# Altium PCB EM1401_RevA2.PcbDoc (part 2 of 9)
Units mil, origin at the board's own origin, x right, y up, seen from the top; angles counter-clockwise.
Board outline 7800 x 5300 mil, 6 copper layers (Top Layer, MidLayer1, MidLayer2, MidLayer3, MidLayer4, Bottom Layer), stack 16.8 mil thick; 751 components, 531 nets, 2554 pads, 1388 vias.
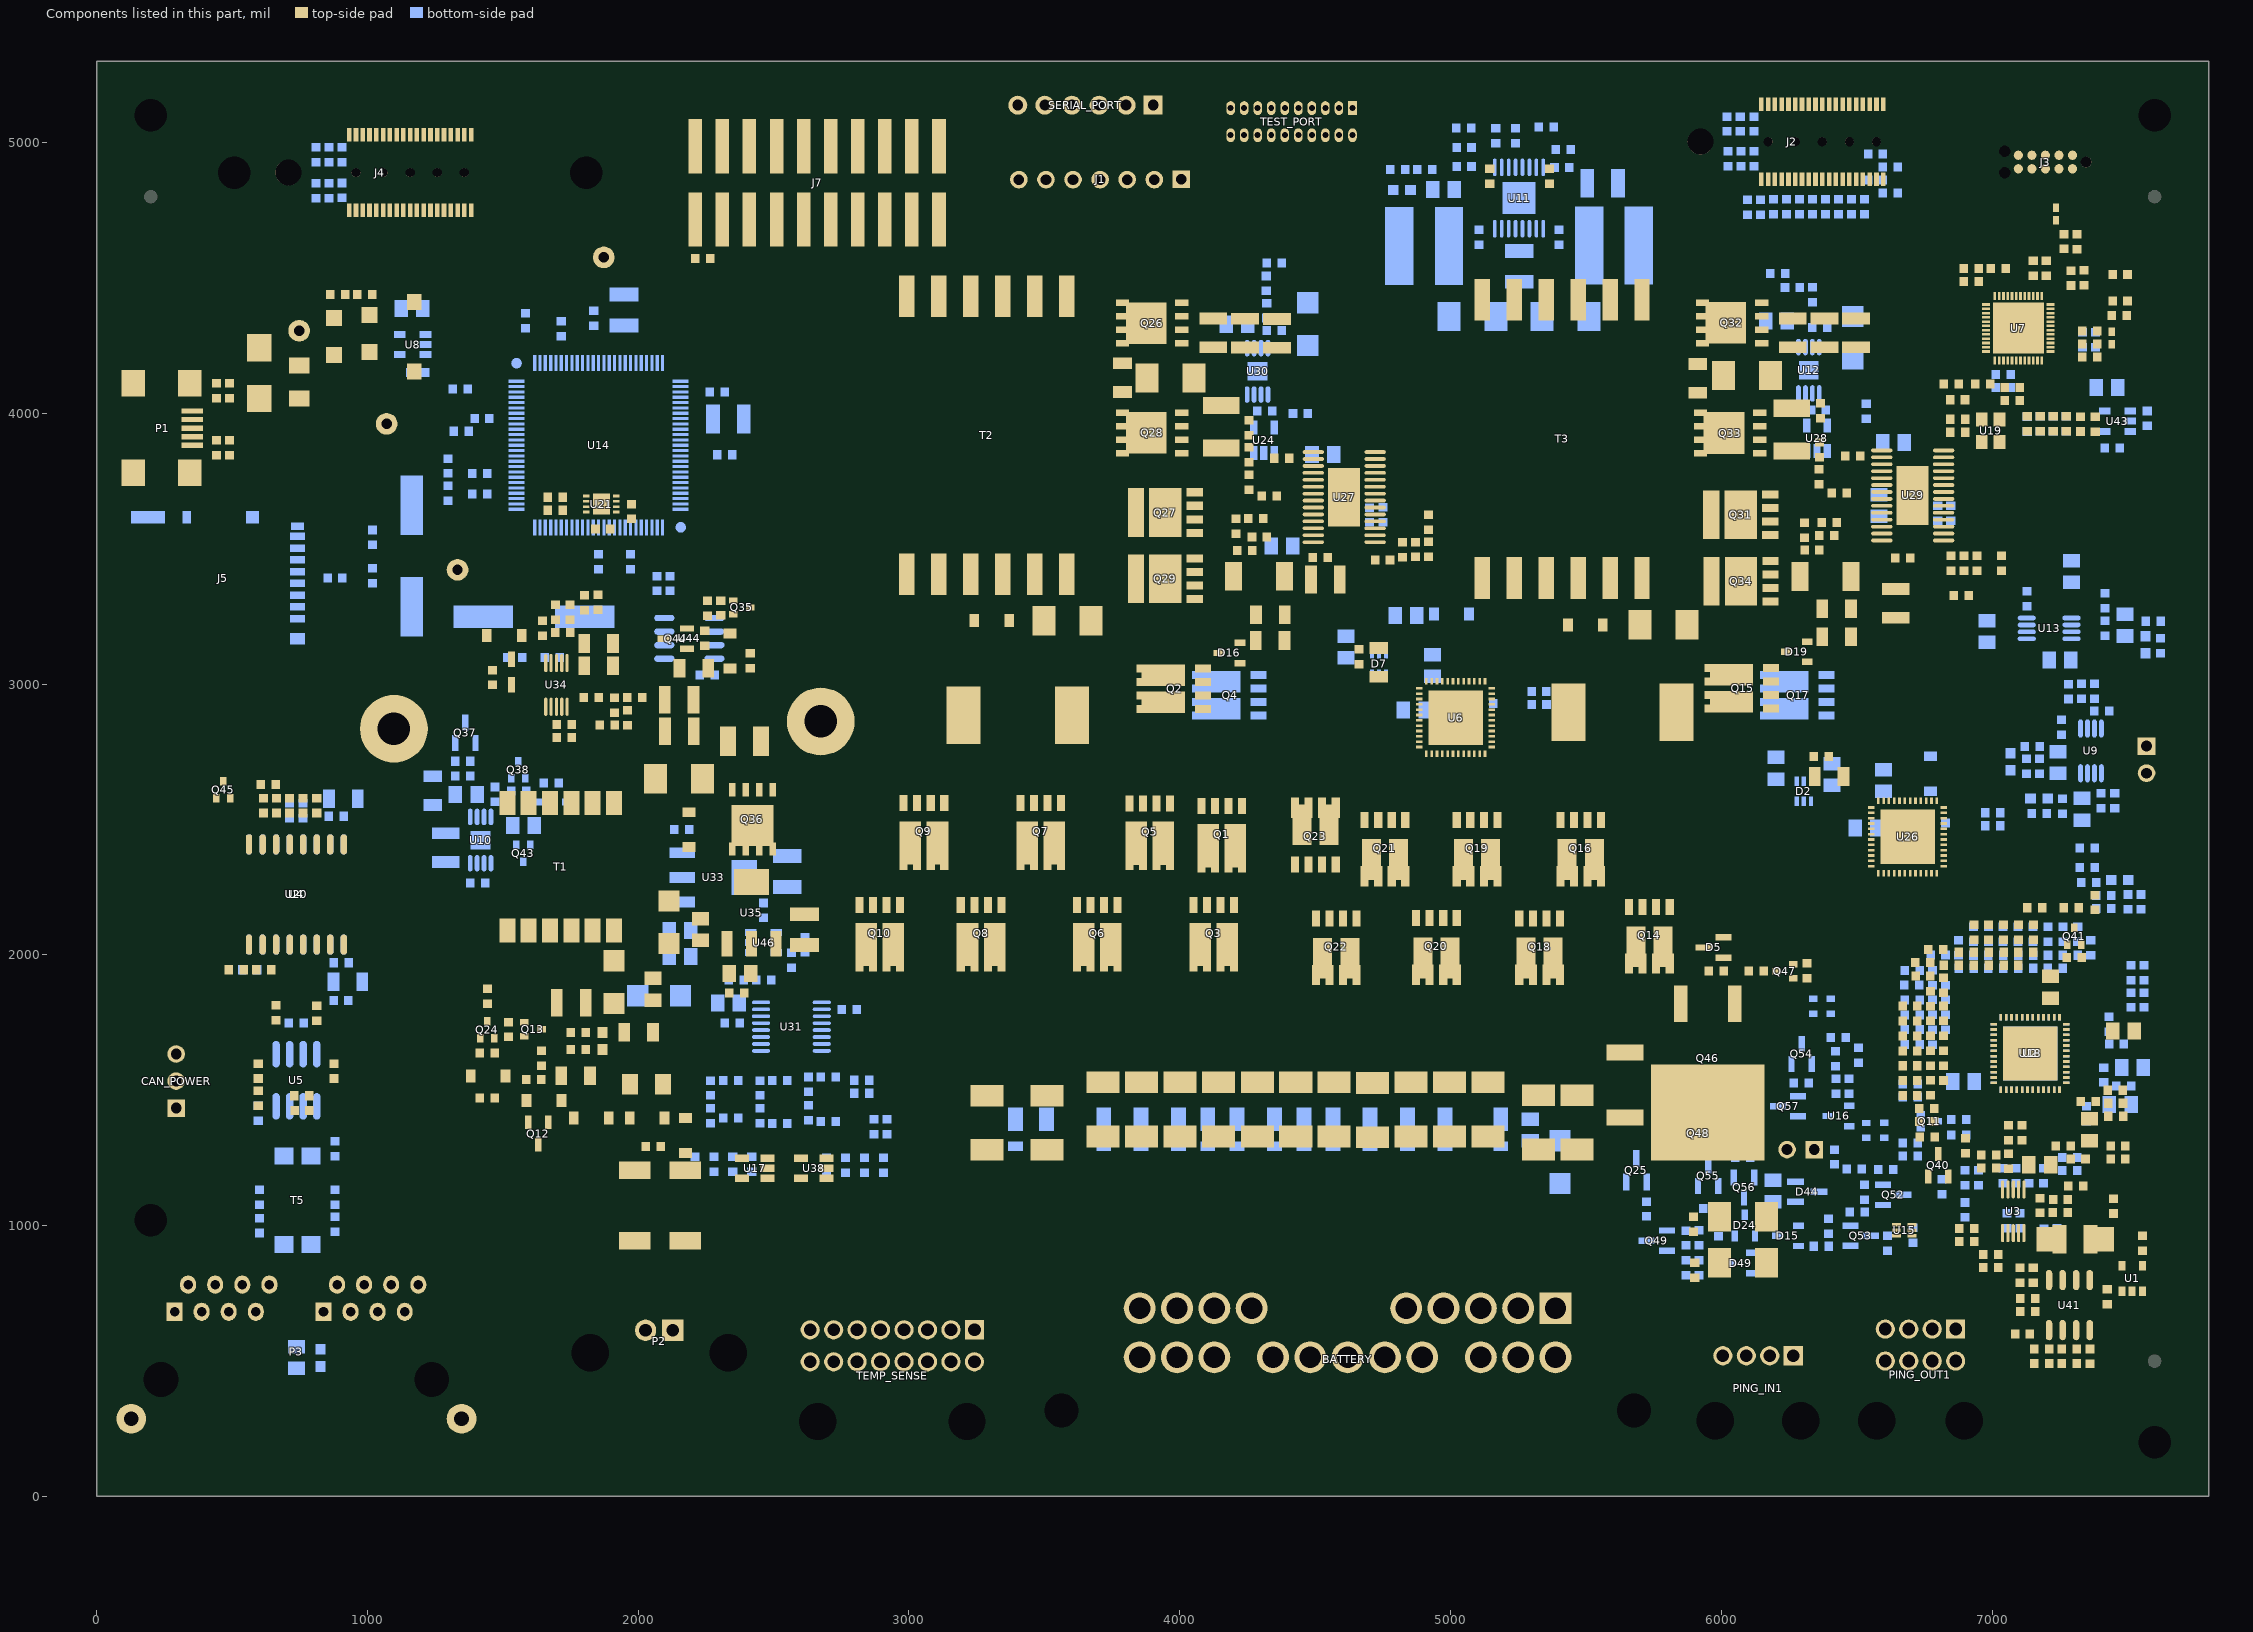
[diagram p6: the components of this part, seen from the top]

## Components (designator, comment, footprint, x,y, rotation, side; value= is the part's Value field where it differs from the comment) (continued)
R227 "CRCW060310K5FKEA" 0603L 1802.5,3301 r90 top
R228 "CRCW06031K15FKEA" 0603L 1851.5,3302 r270 top
R229 "CRCW06030000Z0EA" 0603L 7472.56,4414 r180 top
R230 "CRCW06030000Z0EA" 0603L 7314,4634 r270 top
R231 "CRCW06030000Z0EA" 0603L 7470,4361 r180 top
R232 "CRCW06030000Z0EA" 0603L 7472.56,4512 r180 top
R233 "CRCW06030000Z0EA" 0603L 7266,4634.56 r270 top
R234 "CRCW06030000Z0EA" 0603L 6120,5068.44 r90 bottom
R235 "CRCW06030000Z0EA" 0603L 7183.42,544 r180 top
R236 "CRCW0603100kFKEA" 0603L 4870.42,3497 r270 top
R237 "RC0603FR-07402KL" 0603L 4919,3598 r90 top
R238 "RC0603FR-07402KL" 0603L 6885.91,3327 r180 top
R239 "CRCW0603100kFKEA" 0603L 6943.92,3447 r270 top
R240 "CRCW06030000Z0EA" 0603L 2566,1980.44 r90 bottom
R241 "RT0603DRE07100KL" 0603L 7453,2569.44 r270 bottom
R242 "RT0603DRE07100KL" 0603L 7403,2569.44 r270 bottom
R243 "CRCW060366K5FKEA" 0603L 1988,2950 r0 top
R244 "RT0603DRE07100KL" 0603L 2305,3281 r270 top
R245 "CRCW06030000Z0EA" 0603L 1584,4341.56 r90 bottom
R246 "CRCW060310K0FKEA" 0603L 7330,2973 r90 bottom
R247 "CRCW06031k00FKEA" 0603L 4918.42,3497.44 r90 top
R248 "CRCW06031k00FKEA" 0603L 7035.42,3447 r90 top
R249 "CRCW060310K0FKEA" 0603L 7378,2973.44 r90 bottom
R250 "RT0603DRE07100KL" 0603L 1559.56,2605.5 r0 bottom
R251 "CRCW06031k00FKEA" 0603L 7175,2696.56 r90 bottom
R252 "RT0603DRE07100KL" 0603L 597,1470.44 r270 top
R253 "CRCW06030000Z0EA" 0603L 6097,4761.44 r270 bottom
R254 "CRCW06030000Z0EA" 0603L 6145,4761.44 r270 bottom
R255 "CRCW060349k9FKEA" 0603L 7040.42,1184.44 r270 bottom
R256 "CRCW060349k9FKEA" 0603L 7190.42,1184.44 r270 bottom
R257 "CRCW060349k9FKEA" 0603L 7286.98,1203 r0 bottom
R258 "CRCW06030000Z0EA" 0603L 6193,4762.44 r270 bottom
R259 "CRCW06031K00FKEA" 0603L 6708,964 r270 bottom
R260 "CRCW060320K0FKEA" 0603L 6501.44,1050 r180 bottom
R261 "CRCW0603100KFKEA" 0603L 6529,1124 r270 bottom
R262 "CRCW06031K00FKEA" 0603L 6613,934.56 r270 bottom
R263 "CRCW060320K0FKEA" 0603L 6396,998 r270 bottom
R264 "CRCW0603100KFKEA" 0603L 6368.56,924 r180 bottom
R265 "CRCW060320K0FKEA" 0603L 6296,1527 r0 bottom
R266 "RC0603FR-07680KL" 0603L 6422,1616 r90 bottom
R267 "CRCW06030000Z0EA" 0603L 6241,4762.44 r270 bottom
R268 "CRCW06030000Z0EA" 0603L 6289,4762.44 r270 bottom
R269 "CRCW060320K0FKEA" 0603L 5961.56,1063 r0 bottom
R270 "RC0603FR-07680KL" 0603L 5990,989 r270 bottom
R271 "CRCW06030000Z0EA" 0603L 7457.42,1404 r0 top
R272 "RC0603FR-0739KL" 0603L 6078.56,1299 r180 bottom
R273 "CRCW0603100KFKEA" 0603L 6079,1251 r0 bottom
R274 "RC0603FR-0782KL" 0603L 6424,1515 r90 bottom
R275 "CRCW060325K5FKEA" 0603L 4445.91,4000 r0 bottom
R276 "CRCW06031K50FKEA" 0603L 6472,1515 r270 bottom
R277 "CRCW060325K5FKEA" 0603L 6535.42,4007 r270 bottom
R278 "CRCW060320K0FKEA" 0603L 6418,1253.56 r90 bottom
R279 "CRCW06030000Z0EA" 0603L 7464.98,1246 r0 top
R280 "CRCW06030000Z0EA" 0603L 7464.98,1294 r0 top
R281 "CRCW06030000Z0EA" 0603L 6337,4762.44 r270 bottom
R282 "CRCW06030000Z0EA" 0603L 6385,4763.44 r270 bottom
R283 "CRCW060360R4FKEA" 0603L 757.94,1479.8 r0 top
R284 "CRCW06030000Z0EA" 0603L 6433,4763.44 r270 bottom
R285 "CRCW06030000Z0EA" 0603L 6481,4763.44 r270 bottom
R286 "CRCW060333R0JNEA" 0603L 1694.44,3690 r0 top
R303 "CRCW06030000Z0EA" 0603L 7380,2193.44 r90 top
R304 "CRCW06030000Z0EA" 0603L 6900,1058 r90 bottom
RT1 "NTCG164KF104F" 0603 7471.03,2277 r180 bottom
RT2 "961102-6404-AR" "1X2 100MIL PITCH" 7570.42,2671 r270 top
SERIAL_PORT "961106-6404-AR" "1X6 100MIL PITCH" 3902,5138 r180 top
SW1 "KSR221GLFS" KSR 1173,4283 r270 top
T1 "749196111" 749196111 1714,2326 r0 top
T2 "750311492" "WE EFD20-SMD Transformer" 3287.51,3918.75 r270 top
T3 "750311492" "WE EFD20-SMD Transformer" 5411.96,3905.49 r270 top
T5 "ZJYS81R5-2PL51T-G01" "TDK Choke" 792,930.23 r90 bottom
TEMP_SENSE "1318382-2" 1318382-2 3241.68,615.48 r270 top
TEST_PORT "5-104068-1" 5-104068-1 4638,5027 r0 top
TP1 "TESTPOINT" TESTPOINT 1333,3422 r0 top
TP2 "TESTPOINT" TESTPOINT 1071,3961 r0 top
TP3 "TESTPOINT" TESTPOINT 1873,4576 r0 top
TP5 "TESTPOINT" TESTPOINT 748,4305 r90 bottom
U1 "EMB1441MF" MF05A_L 7517.42,805 r90 top
U2 "EMB1432QSQ" SQA48B 7140.69,1635.92 r270 top
U3 "EMB1426QMM" MUB10A_N 7078.21,1053.13 r270 top
U4 "ISO7521CDWR" "SOIC16 Wide" 738,2223 r90 bottom
U5 "SN65HVDA1040AQDRQ1" M08A_M 738,1537 r270 bottom
U6 "EMB1428QSQ" sqa48a 5018.92,2876.24 r0 top
U7 "AGLN030V5-ZQNG48" QN48_N 7097,4315 r90 top
U8 "EMB1424MF" MF05A_N 1167,4254 r180 bottom
U9 "EMB1466MM" MUA08A_N 7365.2,2753.32 r270 bottom
U10 "TPS7A4001DGN" MUY08A_N 1418,2424 r270 bottom
U11 "LM26400YMH/NOPB" MXA16A_N 5253,4795 r270 bottom
U12 "EMB1412MY" MUY08A_N 6323.42,4159 r90 bottom
U13 "EMB1487MM" MUA08A_N 7210.69,3205.76 r0 bottom
U14 "LM3S5R31-IQC" QFP50P1600X1600X160-100N 1854,3882 r180 bottom
U15 "UCLAMP0506A.TCT" SC-89 6675,983 r180 top
U16 "LM431AIM3" MF03A_L 6433,1405 r180 bottom
U17 "ESDA6V1SC5" MF05A_M 2430.42,1212 r180 top
U18 "EMB1433QSQ" sqa48b 7140.69,1635.92 r0 bottom
U19 "ASE-8.000MHZ-LC-T" ASE-xxxMHz-x-x-x 6995,3936 r90 top
U20 "ISO7520CDWR" "SOIC16 Wide" 738,2223 r90 top
U21 "LMV112SD" SDA08A 1864,3665 r180 top
U24 "BU4S584G2-TR" MF05A_M 4310.82,3900.76 r90 bottom
U26 "EMB1428QSQ" sqa48a 6687.92,2436 r0 top
U27 "EMB1499QMH" MXA28A_M 4607.45,3690.53 r180 top
U28 "BU4S584G2-TR" MF05A_M 6353.42,3908.24 r90 bottom
U29 "EMB1499QMH" MXA28A_M 6706.88,3696.68 r180 top
U30 "EMB1412MY" MUY08A_N 4287.42,4155 r90 bottom
U31 "EMB1402MT" MTC16_N 2565.92,1735 r180 bottom
U33 "EMB1437MP" MP04A_N 2277.59,2286 r0 bottom
U34 "EMB1420MM" MUB10A_N 1698.2,2997.02 r270 top
U35 "EMB1437MP" MP04A_N 2418.42,2155 r90 top
U38 "ESDA6V1SC5" MF05A_M 2648.17,1212 r180 top
U41 "REF5025AID" M08A_L 7285.41,706.65 r90 top
U43 "LP2985AIM5-1.5" MF05A_N 7463,3971 r180 bottom
U44 "25LC512T-I/SN" M08A_L 2189,3169 r0 bottom
U46 "LM4132AMF-3.3" MF05A_N 2463.17,2045.4 r0 bottom
Y1 "ABLSG-4.194304MHZ-D-2-Y-T" "HC-49US crystal" 1163,3473 r90 bottom
Y2 "ABLS2-8.000MHZ-D4Y-T" "HC-49US crystal" 1615,3249 r180 bottom
Zener1 "1SMB5936BT3G" SMB#2 3584.92,3234 r0 top
Zener2 "1SMB5936BT3G" SMB#2 5786.92,3219 r0 top

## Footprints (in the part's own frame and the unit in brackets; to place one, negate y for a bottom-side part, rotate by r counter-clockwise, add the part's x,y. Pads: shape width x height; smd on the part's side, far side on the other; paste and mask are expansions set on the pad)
"1X2 100MIL PITCH" [mm] "100 mil 1x2 header, 230 mil above insulator"
  rect 1.65x1.65 hole 1.016: 1(-2.54,0)
  round 1.65 hole 1.016: 2(0,0)
  silkscreen extent -4.57,-1.52 1.52,1.52
"1X3 100MIL PITCH" [mm] "100 mil 1x3 header, 230 mil above insulator"
  rect 1.65x1.65 hole 1.016: 1(-2.54,0)
  round 1.65 hole 1.016: 2(0,0) 3(2.54,0)
  silkscreen extent -4.93,-1.52 4.06,1.52, body extent -3.81,-1.27 3.81,1.27, height 8.38
"1X6 100MIL PITCH" [mil] "CONN HEADER VERT SGL 6POS"
  rect 70x70 hole 40: 1(0,0)
  round 70 hole 40: 2(100,0) 3(200,0) 4(300,0) 5(400,0) 6(500,0)
  silkscreen extent -50,-50 550,92, body extent -50,-50 550,50, height 69
"2X10 SHROUDED SURFACE MOUNT HDR" [mil] "2X10 Shrouded Surface Mount HDR"
  rect 50x200 smd: 1(0,0) 2(0,270) 3(100,0) 4(100,270) 5(200,0) 6(200,270) 7(300,0) 8(300,270) 9(400,0) 10(400,270) 11(500,0) 12(500,270) 13(600,0) 14(600,270) 15(700,0) 16(700,270) 17(800,0) 18(800,270) 19(900,0) 20(900,270)
  silkscreen extent -196,-99 1095,303, body extent -200,-46 1100,327, height 349
"4-40 SCREW"#1 [mil] "Hole and Pad for 4-40 screw mount"
  round 0 hole 120 unplated: 1(0,0)
  Keep-Out Layer lines w10: 124.64,0 cw(c-0.36,0) 124.64,1
  silkscreen extent -125,-125 125,125
"4-40 SCREW"#2 [mil] "Hole and Pad for 4-40 screw mount"
  round 250 hole 120: 1(0,0)
  Keep-Out Layer circle w10: c-0.36,0 r129.66
  silkscreen extent -137,-137 137,137
5-104068-1 [mm] "AMP 20PIN VERT HEADER ASSY"
  rect 0.8x1.3 hole 0.559: 1(0,2.54)
  oval 0.8x1.3 hole 0.559: 2(0,0) 3(-1.27,2.54) 4(-1.27,0) 5(-2.54,2.54) 6(-2.54,0) 7(-3.81,2.54) 8(-3.81,0) 9(-5.08,2.54) 10(-5.08,0) 11(-6.35,2.54) 12(-6.35,0) 13(-7.62,2.54) 14(-7.62,0) 15(-8.89,2.54) 16(-8.89,0) 17(-10.16,2.54) 18(-10.16,0) 19(-11.43,2.54) 20(-11.43,0)
  silkscreen extent -15.16,-2.34 3.73,6.4, body extent -15.16,-2.34 3.73,6.4, height 11.43
0402 [mm] "0402 from SM-752 data"
  rect 0.8x0.6 smd: 1(-0.6,0) 2(0.6,0)
  silkscreen extent -1.3,-0.6 1.3,0.6, body extent -0.55,-0.3 0.55,0.3, height 0.6
0603 [mm] "0603 from SM-752 data"
  rect 1x0.95 smd: 1(-0.8,0) 2(0.8,0)
  silkscreen extent -1.59,-0.77 1.59,0.77, body extent -0.87,-0.47 0.87,0.47, height 0.85
0603L [mm] "0603 from SM-752 data"
  rect 0.8x0.85 smd: 1(-0.7,0) 2(0.7,0)
  silkscreen extent -0.1,-0.33 0.1,0.33, body extent -0.87,-0.47 0.87,0.47, height 0.85
0805_HV [mil] "0805 with 30mil clearance between pads"
  rect 50x63 smd: 1(-40,0) 2(40,0)
  silkscreen extent -78,-44 78,44, body extent -43,-29 43,29, height 43
0805_Net_Tie#1 [mm]
  rect 1.55x1.6 on Mid7 paste+0 mask+0: 1(-0.75,0)
  rect 1.55x1.6 on Mid7: 2(0.775,0)
0805_Net_Tie#2 [mm]
  rect 1.55x1.6 on Mid5 paste+0 mask+0: 1(-0.75,0)
  rect 1.55x1.6 on Mid5: 2(0.775,0)
1206L [mm] "1206 from SM-752 data"
  rect 1.1x1.75 smd: 1(-1.35,0) 2(1.35,0)
  silkscreen extent -0.4,-0.77 0.4,0.77, body extent -1.7,-0.9 1.7,0.9, height 1.35
1206M [mm]
  rect 1.5x1.95 smd: 1(-1.55,0) 2(1.55,0)
  silkscreen extent -2.76,-1.44 2.76,1.44, body extent -1.7,-0.9 1.7,0.9, height 1.35
1210#1 [mm] "1210 from SM-752 data"
  rect 1.3x2.7 smd: 1(-1.45,0) 2(1.45,0)
  silkscreen extent -2.39,-1.64 2.39,1.64, body extent -1.7,-1.35 1.7,1.35, height 1.35
1210#2 [mm] "1210 STANDARD SIZE"
  rect 1.3x2.7 smd: 1(0,0) 2(2.9,0)
  silkscreen extent -0.94,-1.64 3.84,1.64, body extent -0.25,-1.35 3.15,1.35, height 1.35
1210L [mm] "1210 from SM-752 data"
  rect 1.1x2.6 smd: 1(-1.35,0) 2(1.35,0)
  silkscreen extent -0.4,-1.2 0.4,1.2, body extent -1.7,-1.35 1.7,1.35, height 1.35
1210M [mm] "1210 from SM-752 data"
  rect 1.5x2.8 smd: 1(-1.55,0) 2(1.55,0)
  silkscreen extent -2.75,-1.85 2.75,1.85, body extent -1.7,-1.35 1.7,1.35, height 1.35
1812 [mm]
  rect 1.6x3.4 smd: 1(-2,0) 2(2,0)
  silkscreen extent -0.8,-1.6 0.8,1.6, body extent -2.4,-1.7 2.4,1.7, height 1.35
2010M [mm]
  rect 1.6x2.7 smd: 1(-2.4,0) 2(2.4,0)
  silkscreen extent -3.65,-1.8 3.65,1.8, body extent -2.73,-1.45 2.73,1.45, height 1.66
2512M [mm] "Chip Resistor, Body 6.3x3.2mm, IPC Low Density"
  rect 1.5x3.5 smd: 1(-3.05,0) 2(3.05,0)
  silkscreen extent -1.9,-1.65 1.9,1.65, body extent -3.22,-1.67 3.22,1.67, height 0.71
6032-28 [mm] "Medium Density IPC based on Vishay Sprague 293D datasheet."
  rect 2.55x2.3 smd: 1(-2.375,0) 2(2.375,0)
  silkscreen extent -5.1,-1.75 3.2,2.3, body extent -3.15,-1.75 3.15,1.75, height 2.8
175785 [mm] ".070 SERIES MULTI-LOCK I/O CONN. 20Pos. PCB 90"
  round 1.524 hole 3.2 unplated: 0(9.6,7.35) 0(9.6,-46.35)
  rect 3x3 hole 2: 1(0,0)
  round 3 hole 2: 2(0,-3.5) 3(0,-7) 4(0,-10.5) 5(0,-14) 6(0,-28.5) 7(0,-32) 8(0,-35.5) 9(0,-39) 10(4.6,0) 11(4.6,-3.5) 12(4.6,-7) 13(4.6,-12.5) 14(4.6,-16) 15(4.6,-19.5) 16(4.6,-23) 17(4.6,-26.5) 18(4.6,-32) 19(4.6,-35.5) 20(4.6,-39)
  silkscreen extent -2,-49.65 24.6,10.65, body extent -0.42,-49.65 24.5,10.65, height 15.93
0459002.UR [mil] "Series 459 Littlefuse SMT"
  rect 65x117 smd: 1(-130,0) 2(130,0)
  silkscreen extent -143,-85 143,85, body extent -143,-85 143,85, height 28
1318382-2 [mm] "Tyco 025 Series Multi-Lock Connector 16 position"
  round 3 hole 3.5 unplated: 0(8.6,-0.7) 0(8.6,-14.7)
  rect 1.8x1.8 hole 1.2: 1(0,0)
  round 1.8 hole 1.2: 2(0,-2.2) 3(0,-4.4) 4(0,-6.6) 5(0,-8.8) 6(0,-11) 7(0,-13.2) 8(0,-15.4) 9(3,0) 10(3,-2.2) 11(3,-4.4) 12(3,-6.6) 13(3,-8.8) 14(3,-11) 15(3,-13.2) 16(3,-15.4)
  silkscreen extent -1.4,-19.2 22.6,3.8, body extent -0.3,-19.3 24.17,3.7, height 15.6
1376350-2 [mm] "Tyco 025 Series Multi-Lock Connector 8 position"
  round 3 hole 3.5 unplated: 0(8.6,0.8) 0(8.6,-7.4)
  rect 1.8x1.8 hole 1.2: 1(0,0)
  round 1.8 hole 1.2: 2(0,-2.2) 3(0,-4.4) 4(0,-6.6) 5(3,0) 6(3,-2.2) 7(3,-4.4) 8(3,-6.6)
  silkscreen extent -1.4,-10.4 22.6,3.8, body extent -0.3,-10.4 24.17,3.8, height 15.6
1452625-1 [mm] "Tyco Automotive, Unsealed PCB Horizontal HDR, 2x1"
  round 3 hole 3.5 unplated: 0(2.1,6.47) 0(2.1,-6.47)
  rect 2x2 hole 1.2: 1(0,1.27)
  round 2 hole 1.2: 2(0,-1.27)
  silkscreen extent -1.5,-9.1 22.67,9.1, body extent -0.53,-9.1 22.62,9.1, height 11.2
1565749-1 [mm] "Tyco 025 Series Multi-Lock Connector 4 position"
  round 3 hole 3.5 unplated: 0(6.1,0.7) 0(6.1,-7.3)
  rect 1.8x1.8 hole 1.2: 1(0,0)
  round 1.8 hole 1.2: 2(0,-2.2) 3(0,-4.4) 4(0,-6.6)
  silkscreen extent -1.4,-10.3 20.1,3.7, body extent -0.35,-10.3 21.94,3.7, height 12.58
5767096-8 [mil] "Mictor connector 38 pos receptacle"
  round 94 hole 96: 0(450,0)
  rect 17x50 smd: 1(225,139) 2(225,-139) 3(200,139) 4(200,-139) 5(175,139) 6(175,-139) 7(150,139) 8(150,-139) 9(125,139) 10(125,-139) 11(100,139) 12(100,-139) 13(75,139) 14(75,-139) 15(50,139) 16(50,-139) 17(25,139) 18(25,-139) 19(0,139) 20(0,-139) 21(-25,139) 22(-25,-139) 23(-50,139) 24(-50,-139) 25(-75,139) 26(-75,-139) 27(-100,139) 28(-100,-139) 29(-125,139) 30(-125,-139) 31(-150,139) 32(-150,-139) 33(-175,139) 34(-175,-139) 35(-200,139) 36(-200,-139) 37(-225,139) 38(-225,-139)
  round 32 hole 34: 39(200,0) 40(100,0) 41(0,0) 42(-100,0) 43(-200,0)
  silkscreen extent -500,-190 500,244, body extent -500,-172 500,171, height 240
749196111 [mm] "flyback transformer"
  rect 1.5x2.25 smd: 1(5,5.975) 2(3,5.975) 3(1,5.975) 4(-1,5.975) 5(-3,5.975) 6(-5,5.975) 7(-5,-5.975) 8(-3,-5.975) 9(-1,-5.975) 10(1,-5.975) 11(3,-5.975) 12(5,-5.975)
  silkscreen extent -6.5,-4.5 7,6.78, body extent -6.5,-6.5 6.5,6.5, height 11.43
A00-216-262-450 [mm] "CONN RJ45 MODJACK 1X2 R/A SHIELD"
  round 0 hole 3.251 unplated: 0(-12.7,-6.35) 0(12.7,-6.35)
  round 2.794 hole 1.397: 10(-15.494,-10.033) 10(15.494,-10.033)
  rect 1.5x1.7 hole 0.9: A1(-11.43,0) B1(2.54,0)
  oval 1.5x1.7 hole 0.9: A2(-10.16,2.54) A3(-8.89,0) A4(-7.62,2.54) A5(-6.35,0) A6(-5.08,2.54) A7(-3.81,0) A8(-2.54,2.54) B2(3.81,2.54) B3(5.08,0) B4(6.35,2.54) B5(7.62,0) B6(8.89,2.54) B7(10.16,0) B8(11.43,2.54)
  silkscreen extent -15.49,-17.22 15.49,4.04, body extent -15.49,-17.22 15.63,4.05, height 1.81
ASE-xxxMHz-x-x-x [mil] "ASE 3.3Vdc CMOS SMD crystal oscillator"
  rect 51x43 smd: 1(-41.5,-32.5) 2(41.5,-32.5) 3(41.5,32.5) 4(-41.5,32.5)
  silkscreen extent -102,-89 77,64
CDRH6D28 [mm] "Sumida reommended land pattern"
  rect 2.65x7.3 smd: 1(-2.325,0) 2(2.325,0)
  silkscreen extent -4,-4 4,4, body extent -3.5,-3.5 3.5,3.5, height 3
DDPAK [mil] "D2-PAK, 3-Pads, Body 9.7x10.4mm (max), IPC Medium Density, using Vishay Silionix recommended pad sizes"
  rect 135x49.49 smd: 1(-246.06,100) 3(-246.06,-100)
  rect 355x420 smd: 4(155.51,0)
  silkscreen extent -337,-220 344,220, body extent -116,-205 264,205, height 190
DM3BT-DSF-PEJS [mm] "Hirose DM3 series microSD card connector"
  rect 1.05x1.4 smd: 0(-5.1,0.7)
  rect 0.7x1.2 smd: 0(5.45,0.7)
  rect 1.2x3.2 smd: 0(6.3,-13.3)
  rect 1.2x0.8 smd: 0(6.3,-9.7)
  rect 1.2x1.2 smd: 0(6.3,-3.5)
  rect 0.7x1.4 smd: 1(-3.2,0.7) 2(-2.1,0.7) 3(-1,0.7) 4(0.1,0.7) 5(1.2,0.7) 6(2.3,0.7) 7(3.4,0.7) 8(4.5,0.7)
  Top Layer region: -6.05,-14.75 -5.75,-14.75 -5.75,-15.25 -7.75,-15.25 -7.75,-13.35 -6.25,-13.35 -6.25,-14.55
  Keep-Out Layer region: 6,-2.7 6,0.2 6.8,0.2 6.8,-2.7
  Keep-Out Layer region: 6,-8 6,-4.3 6.8,-4.3 6.8,-8
  silkscreen extent -8,-16.8 7.2,1.7
"HC-49US crystal" [mil]
  rect 220x83 smd: 1(-187,0) 2(187,0)
  silkscreen extent -325,-100 325,100
HSMG-xxx [mm]
  rect 1.5x1.5 smd: 1(-1.75,0) 2(1.75,0)
  silkscreen extent -2.76,-1.44 3.06,1.44, body extent -1.7,-0.9 1.7,0.9, height 1.35
HSMH-xxx [mm]
  rect 1.5x1.5 smd: 1(-1.75,0) 2(1.75,0)
  silkscreen extent -3.06,-1.44 2.76,1.44, body extent -1.7,-0.9 1.7,0.9, height 1.35
KSR [mm] "C&K Components SPST switch"
  rect 1.5x1.4 smd: 1(-3.25,0) 2(3.25,0)
  silkscreen extent -3.2,-2 3.2,2, body extent -3,-1.9 3,1.9, height 2.65
LFPAK [mm] "Renesas LFPAK recommended land pattern  2008-05-26, page 17 of REJ11K0001_surface.pdf"
  rect 0.76x1.52 smd: 1(-1.905,-2.76) 2(-0.635,-2.76) 3(0.635,-2.76) 4(1.905,-2.76)
  rect 4.57x3.04 smd: 5(0,0)
  rect 4.57x1.52 smd: 6(0,2.76)
  silkscreen extent -3.01,-3.63 2.66,3.52, body extent -2.65,-1.97 2.65,1.97, height 1.1
M08A_L [mm] "SOIC, 8-Leads, Body 4.9x3.9mm, Pitch 1.27mm, IPC High Density"
  oval 1.9x0.6 smd: 1(-2.35,1.905) 2(-2.35,0.635) 3(-2.35,-0.635) 4(-2.35,-1.905) 5(2.35,-1.905) 6(2.35,-0.635) 7(2.35,0.635) 8(2.35,1.905)
  silkscreen extent -2.47,-2.5 1,2.88, body extent -2,-2.5 2,2.5, height 1.75
M08A_M [mm] "SOIC, 8-Leads, Body 4.9x3.9mm, Pitch 1.27mm, IPC Low Density"
  oval 2.5x0.7 smd: 1(-2.45,1.905) 2(-2.45,0.635) 3(-2.45,-0.635) 4(-2.45,-1.905) 5(2.45,-1.905) 6(2.45,-0.635) 7(2.45,0.635) 8(2.45,1.905)
  silkscreen extent -2.57,-2.5 0.8,2.93, body extent -2,-2.5 2,2.5, height 1.75
MF03A_L [mm] "SOT23, 3-Leads, Body 2.9x1.3mm, Pitch 0.95mm, Lead Span 2.4mm, IPC High Density"
  rect 1x0.6 smd: 1(-1,0.95) 2(-1,-0.95) 3(1,0)
  silkscreen extent -1.13,-1.5 0.7,1.92, body extent -0.7,-1.5 0.7,1.5, height 1.12
MF03A_M [mm] "SOT23, 3-Leads, Body 2.9x1.3mm, Pitch 0.95mm, Lead Span 2.4mm, IPC Low Density"
  rect 1.6x0.6 smd: 1(-1.1,0.95) 2(-1.1,-0.95) 3(1.1,0)
  silkscreen extent -1.22,-1.5 0.7,1.92, body extent -0.7,-1.5 0.7,1.5, height 1.12
MF03A_N [mm]
  rect 1.3x0.6 smd: 1(-1.05,0.95) 2(-1.05,-0.95) 3(1.05,0)
  silkscreen extent -1.17,-1.5 0.7,1.93, body extent -0.7,-1.5 0.7,1.5, height 1.12
MF05A_L [mm] "SOT23, 5-Leads, Body 2.9x1.6mm, Pitch 0.95mm, Lead Span 2.8mm, IPC High Density"
  rect 0.9x0.65 smd: 1(-1.2,0.95) 2(-1.2,0) 3(-1.2,-0.95) 4(1.2,-0.95) 5(1.2,0.95)
  silkscreen extent -2.36,-1.55 0.35,1.55, body extent -0.9,-1.55 0.9,1.55, height 1.22
MF05A_M [mm] "SOT23, 5-Leads, Body 2.9x1.6mm, Pitch 0.95mm, Lead Span 2.8mm, IPC Low Density"
  rect 1.3x0.7 smd: 1(-1.2,0.95) 2(-1.2,0) 3(-1.2,-0.95) 4(1.2,-0.95) 5(1.2,0.95)
  silkscreen extent -1.33,-1.55 0.15,1.97, body extent -0.9,-1.55 0.9,1.55, height 1.22
MF05A_N [mm] "SOT23, 5-Leads, Body 2.9x1.6mm, Pitch 0.95mm, Lead Span 2.8mm, IPC Medium Density"
  rect 1.1x0.65 smd: 1(-1.2,0.95) 2(-1.2,0) 3(-1.2,-0.95) 4(1.2,-0.95) 5(1.2,0.95)
  silkscreen extent -1.33,-1.55 0.25,1.95, body extent -0.9,-1.55 0.9,1.55, height 1.19
MP04A_N [mm] "SOT223, 4-Leads, Body 6.5x3.5mm, Pitch 2.3mm, Lead Span 7mm, IPC Medium Density"
  rect 2.4x1 smd: 1(-2.9,2.3) 2(-2.9,0) 3(-2.9,-2.3)
  rect 2.4x3.3 smd: 4(2.9,0)
  silkscreen extent -3.02,-3.35 1.4,3.47, body extent -1.85,-3.35 1.85,3.35, height 1.8
MTC16_N [mm] "TSOP, 16-Leads, Body 5x4.4mm, Pitch 0.65mm, IPC Medium Density"
  oval 1.7x0.35 smd: 1(-2.85,2.275) 2(-2.85,1.625) 3(-2.85,0.975) 4(-2.85,0.325) 5(-2.85,-0.325) 6(-2.85,-0.975) 7(-2.85,-1.625) 8(-2.85,-2.275) 9(2.85,-2.275) 10(2.85,-1.625) 11(2.85,-0.975) 12(2.85,-0.325) 13(2.85,0.325) 14(2.85,0.975) 15(2.85,1.625) 16(2.85,2.275)
  silkscreen extent -2.98,-2.55 1.6,3.12, body extent -2.25,-2.55 2.25,2.55, height 1.1
MUA08A_N [mm]
  oval 1.7x0.45 smd: 1(-2.1,0.975) 2(-2.1,0.325) 3(-2.1,-0.325) 4(-2.1,-0.975) 5(2.1,-0.975) 6(2.1,-0.325) 7(2.1,0.325) 8(2.1,0.975)
  silkscreen extent -2.22,-1.55 0.85,1.87, body extent -1.6,-1.6 1.6,1.6, height 1.09
MUB10A_N [mm] "TSSOP, 10-Leads, Body 3x3mm, Pitch 0.5mm, IPC Medium Density"
  oval 1.7x0.3 smd: 1(-2.05,1) 2(-2.05,0.5) 3(-2.05,0) 4(-2.05,-0.5) 5(-2.05,-1) 6(2.05,-1) 7(2.05,-0.5) 8(2.05,0) 9(2.05,0.5) 10(2.05,1)
  silkscreen extent -2.17,-1.6 0.8,1.83, body extent -1.6,-1.6 1.6,1.6, height 1.09
MUY08A_N [mm] "TSOP, 8-Leads, Body 3x3mm, Pitch 0.65mm, Exposed Pad, IPC Medium Density"
  oval 1.55x0.45 smd: 1(-2.175,0.975) 2(-2.175,0.325) 3(-2.175,-0.325) 4(-2.175,-0.975) 5(2.175,-0.975) 6(2.175,-0.325) 7(2.175,0.325) 8(2.175,0.975)
  rect 1.73x1.85 smd: 9(0,0)
  silkscreen extent -2.3,-1.55 1,1.87, body extent -1.55,-1.55 1.55,1.55, height 1.09
MXA16A_N [mm] "TSOP, 16-Leads, Body 5x4.4mm, Pitch 0.65mm, Exposed Pad, IPC Medium Density"
  oval 1.65x0.35 smd: 1(-2.875,2.275) 2(-2.875,1.625) 3(-2.875,0.975) 4(-2.875,0.325) 5(-2.875,-0.325) 6(-2.875,-0.975) 7(-2.875,-1.625) 8(-2.875,-2.275) 9(2.875,-2.275) 10(2.875,-1.625) 11(2.875,-0.975) 12(2.875,-0.325) 13(2.875,0.325) 14(2.875,0.975) 15(2.875,1.625) 16(2.875,2.275)
  rect 3x3.1 smd: 17(0,0)
  silkscreen extent -3,-2.55 1.5,3.12, body extent -2.25,-2.55 2.25,2.55, height 1.1
MXA28A_M [mm] "TSOP, 28-Leads, Body 9.7x4.4mm, Pitch 0.65mm, Exposed Pad, IPC Low Density"
  oval 2x0.35 smd: 1(-2.9,4.225) 2(-2.9,3.575) 3(-2.9,2.925) 4(-2.9,2.275) 5(-2.9,1.625) 6(-2.9,0.975) 7(-2.9,0.325) 8(-2.9,-0.325) 9(-2.9,-0.975) 10(-2.9,-1.625) 11(-2.9,-2.275) 12(-2.9,-2.925) 13(-2.9,-3.575) 14(-2.9,-4.225) 15(2.9,-4.225) 16(2.9,-3.575) 17(2.9,-2.925) 18(2.9,-2.275) 19(2.9,-1.625) 20(2.9,-0.975) 21(2.9,-0.325) 22(2.9,0.325) 23(2.9,0.975) 24(2.9,1.625) 25(2.9,2.275) 26(2.9,2.925) 27(2.9,3.575) 28(2.9,4.225)
  rect 3x5.5 smd: 29(0,0)
  silkscreen extent -3.03,-4.9 1.5,5.07, body extent -2.25,-4.9 2.25,4.9, height 1.1
POWERDI123 [mm] "Diodes Inc recommended land pattern, document number DS30628 Rev. 6-2"
  rect 2.2x1.4 smd: 1(-1.275,0)
  rect 0.9x1.4 smd: 2(1.275,0)
  silkscreen extent -3.19,-1.02 1.76,1.02, body extent -1.5,-0.97 1.5,0.96, height 1
"POWERPAK SO-8 -Dual"#1 [mm] "Dual N-CHANNEL 40V MOSFET, POWERPAK SO-8 , VISHAY"
  rect 1.5x0.762 smd mask+0.076: 1(-2.65,1.905) 2(-2.65,0.635) 3(-2.65,-0.635) 4(-2.65,-1.905)
  rect 1.9x0.762 smd mask+0.076: 5(2.65,-1.905) 6(2.65,-0.635) 7(2.65,0.635) 8(2.65,1.905)
  rect 4.064x2.032 smd mask+0.076: 6(1.075,-1.27) 8(1.075,1.27)
  silkscreen extent -3.67,-2.9 3.88,3.43
"POWERPAK SO-8 -Dual"#2 [mm] "Dual N-CHANNEL 40V MOSFET, POWERPAK SO-8 , VISHAY"
  rect 1.5x0.762 smd mask+0.076: 1(-2.65,1.905) 2(-2.65,0.635) 3(-2.65,-0.635) 4(-2.65,-1.905)
  rect 1.9x0.762 smd mask+0.076: 5(2.65,-1.905) 6(2.65,-0.635) 7(2.65,0.635) 8(2.65,1.905)
  rect 3.81x1.778 smd: 6(1.075,-1.27) 8(1.075,1.27)
  silkscreen extent -3.67,-2.9 3.88,3.43
PowerPAK_SO-8 [mil] "Vishay PowerPAK SO-8, Body 5.3x6.0mm (max), Pitch 1.27mm, IPC Medium Density"
  rect 50x24 smd mask+2.99: 1(-109.5,75) 2(-109.5,25) 3(-109.5,-25) 4(-109.5,-75)
  rect 48x24 smd mask+2.99: 5(109.5,-75) 8(109.5,75)
  rect 48x24 smd paste-12 mask+2.99: 6(109.5,-25) 7(109.5,25)
  rect 150x154 smd paste-75 mask+2.99: 9(22.5,0)
  silkscreen extent -114,-104 62,113, body extent -121,-102 121,102, height 43
QFP50P1600X1600X160-100N [mm]
  rect 1.5x0.3 smd: 1(-7.7,6) 2(-7.7,5.5) 3(-7.7,5) 4(-7.7,4.5) 5(-7.7,4) 6(-7.7,3.5) 7(-7.7,3) 8(-7.7,2.5) 9(-7.7,2) 10(-7.7,1.5) 11(-7.7,1) 12(-7.7,0.5) 13(-7.7,0) 14(-7.7,-0.5) 15(-7.7,-1) 16(-7.7,-1.5) 17(-7.7,-2) 18(-7.7,-2.5) 19(-7.7,-3) 20(-7.7,-3.5) 21(-7.7,-4) 22(-7.7,-4.5) 23(-7.7,-5) 24(-7.7,-5.5) 25(-7.7,-6) 51(7.7,-6) 52(7.7,-5.5) 53(7.7,-5) 54(7.7,-4.5) 55(7.7,-4) 56(7.7,-3.5) 57(7.7,-3) 58(7.7,-2.5) 59(7.7,-2) 60(7.7,-1.5) 61(7.7,-1) 62(7.7,-0.5) 63(7.7,0) 64(7.7,0.5) 65(7.7,1) 66(7.7,1.5) 67(7.7,2) 68(7.7,2.5) 69(7.7,3) 70(7.7,3.5) 71(7.7,4) 72(7.7,4.5) 73(7.7,5) 74(7.7,5.5) 75(7.7,6)
  rect 0.3x1.5 smd: 26(-6,-7.7) 27(-5.5,-7.7) 28(-5,-7.7) 29(-4.5,-7.7) 30(-4,-7.7) 31(-3.5,-7.7) 32(-3,-7.7) 33(-2.5,-7.7) 34(-2,-7.7) 35(-1.5,-7.7) 36(-1,-7.7) 37(-0.5,-7.7) 38(0,-7.7) 39(0.5,-7.7) 40(1,-7.7) 41(1.5,-7.7) 42(2,-7.7) 43(2.5,-7.7) 44(3,-7.7) 45(3.5,-7.7) 46(4,-7.7) 47(4.5,-7.7) 48(5,-7.7) 49(5.5,-7.7) 50(6,-7.7) 76(6,7.7) 77(5.5,7.7) 78(5,7.7) 79(4.5,7.7) 80(4,7.7) 81(3.5,7.7) 82(3,7.7) 83(2.5,7.7) 84(2,7.7) 85(1.5,7.7) 86(1,7.7) 87(0.5,7.7) 88(0,7.7) 89(-0.5,7.7) 90(-1,7.7) 91(-1.5,7.7) 92(-2,7.7) 93(-2.5,7.7) 94(-3,7.7) 95(-3.5,7.7) 96(-4,7.7) 97(-4.5,7.7) 98(-5,7.7) 99(-5.5,7.7) 100(-6,7.7)
  round 1 smd mask+0.5: 101(-7.7,-7.7) 102(7.7,7.7)
  Top Layer keep-out region: -6.7,-7.7 -6.776,-7.317 -6.993,-6.993 -7.317,-6.776 -7.7,-6.7 -7.7,-6.7 -8.083,-6.776 -8.407,-6.993 -8.624,-7.317 -8.7,-7.7 -8.7,-7.7 -8.624,-8.083 -8.407,-8.407 -8.083,-8.624 -7.7,-8.7 -7.7,-8.7 -7.317,-8.624 -6.993,-8.407 -6.776,-8.083 -6.7,-7.7
  Top Layer keep-out region: 8.7,7.7 8.624,8.083 8.407,8.407 8.083,8.624 7.7,8.7 7.7,8.7 7.317,8.624 6.993,8.407 6.776,8.083 6.7,7.7 6.7,7.7 6.776,7.317 6.993,6.993 7.317,6.776 7.7,6.7 7.7,6.7 8.083,6.776 8.407,6.993 8.624,7.317 8.7,7.7
  silkscreen extent -8.32,-6.55 6.55,6.82
QN48_N [mm] "QFN, 48-Leads, Body 6x6 mm, Pitch 0.4mm, IPC Medium Density"
  rect 0.75x0.25 smd: 1(-3.025,2.2) 2(-3.025,1.8) 3(-3.025,1.4) 4(-3.025,1) 5(-3.025,0.6) 6(-3.025,0.2) 7(-3.025,-0.2) 8(-3.025,-0.6) 9(-3.025,-1) 10(-3.025,-1.4) 11(-3.025,-1.8) 12(-3.025,-2.2) 25(3.025,-2.2) 26(3.025,-1.8) 27(3.025,-1.4) 28(3.025,-1) 29(3.025,-0.6) 30(3.025,-0.2) 31(3.025,0.2) 32(3.025,0.6) 33(3.025,1) 34(3.025,1.4) 35(3.025,1.8) 36(3.025,2.2)
  rect 0.25x0.75 smd: 13(-2.2,-3.025) 14(-1.8,-3.025) 15(-1.4,-3.025) 16(-1,-3.025) 17(-0.6,-3.025) 18(-0.2,-3.025) 19(0.2,-3.025) 20(0.6,-3.025) 21(1,-3.025) 22(1.4,-3.025) 23(1.8,-3.025) 24(2.2,-3.025) 37(2.2,3.025) 38(1.8,3.025) 39(1.4,3.025) 40(1,3.025) 41(0.6,3.025) 42(0.2,3.025) 43(-0.2,3.025) 44(-0.6,3.025) 45(-1,3.025) 46(-1.4,3.025) 47(-1.8,3.025) 48(-2.2,3.025)
  rect 4.8x4.8 smd paste-2.4 mask+0.062: 49(0,0)
  silkscreen extent -3.9,-3.13 3.13,3.13, body extent -3.07,-3.07 3.07,3.07, height 1
SC-89 [mil] "SOT23, 5-Leads, Body .5mm pitch 1.5mm x 1.5mm body"
  rect 33x12 smd: 1(-28.5,20) 2(-28.5,0) 3(-28.5,-20) 4(28.5,-20) 5(28.5,0) 6(28.5,20)
  silkscreen extent -47,43 -33,56, body extent -31,-31 31,31, height 48
SDA08A [mm] "SON, 8-Leads, Body 3x3mm, Pitch 0.5mm, NSC Recommended"
  rect 0.6x0.25 smd paste-0.125 mask+0.051: 1(-1.4,0.75) 2(-1.4,0.25) 3(-1.4,-0.25) 4(-1.4,-0.75) 5(1.4,-0.75) 6(1.4,-0.25) 7(1.4,0.25) 8(1.4,0.75)
  rect 1.6x2 smd paste-0.05 mask+0.051: 9(0,0)
  silkscreen extent -2.03,-1.7 1.85,2.28, body extent -1.55,-1.55 1.55,1.55, height 0.8
SMA [mm] "Molded Diode, 2-Leads, Body 4.3x2.6mm, IPC Medium Density, based on OnSemi component dimensions and land pattern"
  rect 2x2 smd: 1(2,0) 2(-2,0)
  silkscreen extent -2.3,-1.5 3.43,1.5, body extent -2.29,-1.46 2.28,1.46, height 2.27
SMB#1 [mil] "Molded Diode, 2-Leads, Body 5.4x3.6mm, IPC Medium Density, based on OnSemi component dimensions"
  rect 85x107.99 smd: 1(87.01,0) 2(-87.01,0)
  silkscreen extent -110,-79 150,79, body extent -110,-78 110,78, height 96
SMB#2 [mil] "Molded Diode, 2-Leads, Body 5.4x3.6mm, IPC Medium Density, based on OnSemi component dimensions"
  rect 85x107.99 smd: 1(-87.01,0) 2(87.01,0)
  silkscreen extent -110,-79 110,79, body extent -110,-78 110,78, height 96
"SOD523 TVS" [mm] "SOD footpirnt - TVS ESD Bidirectional"
  rect 0.6x0.8 smd: 1(-0.7,0) 2(0.7,0)
  silkscreen extent -1.73,-0.7 1.3,0.7, body extent -0.65,-0.45 0.65,0.45, height 0.7
SOD-123#1 [mm] "On Semi recommended land pattern"
  rect 0.915x1.22 smd: 1(1.637,0) 2(-1.637,0)
  silkscreen extent -1.68,-1.14 2.39,1.14, body extent -1.42,-0.9 1.42,0.9, height 1.35
SOD-123#2 [mm] "On Semi recommended land pattern"
  rect 0.915x1.22 smd: 1(-1.637,0) 2(1.637,0)
  silkscreen extent -1.68,-1.14 1.68,1.14, body extent -1.42,-0.9 1.42,0.9, height 1.35
sod-323 [mm]
  rect 0.65x1.45 smd: 1(0,-1.2) 2(0,1.2)
  silkscreen extent -0.93,-1.28 0.92,0.97
SOD-323 [mm]
  rect 0.65x1.45 smd: 1(0,-1.2) 2(0,1.2)
  silkscreen extent -0.93,-1.28 0.92,0.97
"SOIC16 Wide" [mm]
  oval 1.9x0.6 smd: 1(-4.7,4.445) 2(-4.7,3.175) 3(-4.7,1.905) 4(-4.7,0.635) 5(-4.7,-0.635) 6(-4.7,-1.905) 7(-4.7,-3.175) 8(-4.7,-4.445) 9(4.7,-4.445) 10(4.7,-3.175) 11(4.7,-1.905) 12(4.7,-0.635) 13(4.7,0.635) 14(4.7,1.905) 15(4.7,3.175) 16(4.7,4.445)
  silkscreen extent -4.82,-5.25 3.3,5.42, body extent -3.95,-5.25 3.95,5.25, height 2.65
SOT-23 [mm] "SOT23, 3-Leads, Body 2.9x1.3mm, Pitch 0.95mm, Lead Span 2.5mm, IPC Medium Density"
  rect 1.5x0.6 smd: 1(-0.95,0.95) 2(-0.95,-0.95) 3(0.95,0)
  silkscreen extent -2.48,-1.5 0.7,1.65, body extent -1.16,-1.45 1.21,1.45, height 1
SOT-323 [mm] "SC-70-3 and SOT-323 footrpint"
  rect 0.8x0.6 smd: 1(-0.8,0.65) 2(-0.8,-0.65) 3(0.8,0)
  silkscreen extent -1.62,-1.22 1.09,1.34, body extent -0.72,-1.1 0.72,1.1, height 1.1
SOT-363 [mil] "SOT-363 FOOTPRINT"
  rect 16x35 smd: 1(0,0) 2(26,0) 3(52,0) 4(52,75) 5(26,75) 6(0,75)
  silkscreen extent -24,-41 75,62
sqa48a [mm] "QFN, 48-Leads, Body 7x7mm, Pitch 0.5mm, NSC Recommended"
  rect 0.6x0.25 smd paste-0.125 mask+0.051: 1(-3.4,2.75) 2(-3.4,2.25) 3(-3.4,1.75) 4(-3.4,1.25) 5(-3.4,0.75) 6(-3.4,0.25) 7(-3.4,-0.25) 8(-3.4,-0.75) 9(-3.4,-1.25) 10(-3.4,-1.75) 11(-3.4,-2.25) 12(-3.4,-2.75) 25(3.4,-2.75) 26(3.4,-2.25) 27(3.4,-1.75) 28(3.4,-1.25) 29(3.4,-0.75) 30(3.4,-0.25) 31(3.4,0.25) 32(3.4,0.75) 33(3.4,1.25) 34(3.4,1.75) 35(3.4,2.25) 36(3.4,2.75)
  rect 0.25x0.6 smd paste-0.125 mask+0.051: 13(-2.75,-3.4) 14(-2.25,-3.4) 15(-1.75,-3.4) 16(-1.25,-3.4) 17(-0.75,-3.4) 18(-0.25,-3.4) 19(0.25,-3.4) 20(0.75,-3.4) 21(1.25,-3.4) 22(1.75,-3.4) 23(2.25,-3.4) 24(2.75,-3.4) 37(2.75,3.4) 38(2.25,3.4) 39(1.75,3.4) 40(1.25,3.4) 41(0.75,3.4) 42(0.25,3.4) 43(-0.25,3.4) 44(-0.75,3.4) 45(-1.25,3.4) 46(-1.75,3.4) 47(-2.25,3.4) 48(-2.75,3.4)
  rect 5.1x5.1 smd paste-2.55 mask+0.051: 49(0,0)
  silkscreen extent -4.52,-3.85 3.85,3.85, body extent -3.55,-3.55 3.55,3.55, height 0.8
SQA48B [mm] "QFN, 48-Leads, Body 7x7mm, Pitch 0.5mm, NSC Recommended"
  rect 0.6x0.25 smd paste-0.125 mask+0.051: 1(-3.4,2.75) 2(-3.4,2.25) 3(-3.4,1.75) 4(-3.4,1.25) 5(-3.4,0.75) 6(-3.4,0.25) 7(-3.4,-0.25) 8(-3.4,-0.75) 9(-3.4,-1.25) 10(-3.4,-1.75) 11(-3.4,-2.25) 12(-3.4,-2.75) 25(3.4,-2.75) 26(3.4,-2.25) 27(3.4,-1.75) 28(3.4,-1.25) 29(3.4,-0.75) 30(3.4,-0.25) 31(3.4,0.25) 32(3.4,0.75) 33(3.4,1.25) 34(3.4,1.75) 35(3.4,2.25) 36(3.4,2.75)
  rect 0.25x0.6 smd paste-0.125 mask+0.051: 13(-2.75,-3.4) 14(-2.25,-3.4) 15(-1.75,-3.4) 16(-1.25,-3.4) 17(-0.75,-3.4) 18(-0.25,-3.4) 19(0.25,-3.4) 20(0.75,-3.4) 21(1.25,-3.4) 22(1.75,-3.4) 23(2.25,-3.4) 24(2.75,-3.4) 37(2.75,3.4) 38(2.25,3.4) 39(1.75,3.4) 40(1.25,3.4) 41(0.75,3.4) 42(0.25,3.4) 43(-0.25,3.4) 44(-0.75,3.4) 45(-1.25,3.4) 46(-1.75,3.4) 47(-2.25,3.4) 48(-2.75,3.4)
  rect 5.1x5.1 smd paste-2.55 mask+0.051: 49(0,0)
  silkscreen extent -4.52,-3.85 3.85,3.85, body extent -3.55,-3.55 3.55,3.55, height 0.8
sqa48b [mm] "QFN, 48-Leads, Body 7x7mm, Pitch 0.5mm, NSC Recommended"
  rect 0.6x0.25 smd paste-0.125 mask+0.051: 1(-3.4,2.75) 2(-3.4,2.25) 3(-3.4,1.75) 4(-3.4,1.25) 5(-3.4,0.75) 6(-3.4,0.25) 7(-3.4,-0.25) 8(-3.4,-0.75) 9(-3.4,-1.25) 10(-3.4,-1.75) 11(-3.4,-2.25) 12(-3.4,-2.75) 25(3.4,-2.75) 26(3.4,-2.25) 27(3.4,-1.75) 28(3.4,-1.25) 29(3.4,-0.75) 30(3.4,-0.25) 31(3.4,0.25) 32(3.4,0.75) 33(3.4,1.25) 34(3.4,1.75) 35(3.4,2.25) 36(3.4,2.75)
  rect 0.25x0.6 smd paste-0.125 mask+0.051: 13(-2.75,-3.4) 14(-2.25,-3.4) 15(-1.75,-3.4) 16(-1.25,-3.4) 17(-0.75,-3.4) 18(-0.25,-3.4) 19(0.25,-3.4) 20(0.75,-3.4) 21(1.25,-3.4) 22(1.75,-3.4) 23(2.25,-3.4) 24(2.75,-3.4) 37(2.75,3.4) 38(2.25,3.4) 39(1.75,3.4) 40(1.25,3.4) 41(0.75,3.4) 42(0.25,3.4) 43(-0.25,3.4) 44(-0.75,3.4) 45(-1.25,3.4) 46(-1.75,3.4) 47(-2.25,3.4) 48(-2.75,3.4)
  rect 5.1x5.1 smd paste-2.55 mask+0.051: 49(0,0)
  silkscreen extent -4.24,-3.85 3.85,4.36, body extent -3.55,-3.55 3.55,3.55, height 0.8
SSQ8A [mil] "Bel Fuse SMT Quick Acting Fuse"
  rect 80x122.05 smd: 1(0,0) 2(200,0)
  silkscreen extent 49,-50 149,50, body extent 0,-50 200,50, height 100
TC2050-IDC-NL-10 [mil]
  round 39 hole 42 unplated: 0(-150,0) 0(150,-40) 0(150,40)
  round 34 smd: 1(-100,-25) 2(-50,-25) 3(0,-25) 4(50,-25) 5(100,-25) 6(100,25) 7(50,25) 8(0,25) 9(-50,25) 10(-100,25)
  Keep-Out Layer region: -6.61,0 -25,18.38 -43.38,0 -25,-18.38
  Keep-Out Layer region: -56.61,0 -75,18.38 -93.38,0 -75,-18.38
  Keep-Out Layer region: 43.39,0 25,18.38 6.62,0 25,-18.38
  Keep-Out Layer region: 93.39,0 75,18.38 56.62,0 75,-18.38
  Keep-Out Layer lines w10: 75.02,25 cw(c50,25) 50,-0.02 ; 74.82,25 ccw(c100,25) 100,-0.18 ccw(c100,-25) 75.18,-25 ccw(c50,-25) 50,0.18 ; -24.98,-25 ccw(c-50,-25) -50,0.02 ; -25.08,-25 cw(c0,-25) 0,0.08 ; -74.98,25 cw(c-100,25) -100,-0.02 ; -75.08,25 ccw(c-50,25) -50,-0.08 ; -100,0.08 cw(c-100,-25) -74.92,-25 cw(c-50,-25) -50,-0.08 ; 0,0.08 cw(c0,25) -24.92,25 cw(c-50,25) -50,-0.08 ; 0,0.08 cw(c0,-25) 25.08,-25 cw(c50,-25) 50,-0.08 cw(c50,25) 24.92,25 cw(c0,25) 0,0.08
  silkscreen extent -246,-132 245,132
"TDK Choke" [mm]
  rect 1.6x1.8 smd: 1(0,0) 2(0,-2.54) 3(8.3,-2.54) 4(8.3,0)
  silkscreen extent -1.15,-3.8 9.5,1.3
TESTPOINT [mil]
  round 80 hole 37.99: 1(0,0)
TI_Logo_CopperSolderMask_1p1_x_p275 [mil]
  Top Layer region: 256 vertices and 0 holes, not listed, extent 401.59,-124.43 470.2,-51.18
  Top Layer region: 376 vertices and 0 holes, not listed, extent 472.98,-125.36 533.25,-50.25
  Top Layer region: 290 vertices and 0 holes, not listed, extent 256.94,-124.43 323.7,-51.18
  Top Layer region: 380 vertices and 0 holes, not listed, extent 15.85,-14.09 75.2,61.02
  Top Layer region: 259 vertices and 0 holes, not listed, extent -66.67,-124.43 1.95,-51.18
  Top Layer region: 494 vertices and 0 holes, not listed, extent 325.55,-125.36 399.73,-51.18
  Top Layer region: 641 vertices and 0 holes, not listed, extent 158.65,-125.36 251.37,-51.18
  Top Layer region: 322 vertices and 1 holes, not listed, extent 3.8,-125.36 83.54,-51.18
  Top Layer region: 379 vertices and 0 holes, not listed, extent -126.01,-125.36 -65.74,-50.25
  Top Layer region: 371 vertices and 0 holes, not listed, extent 77.05,-125.36 154.01,-51.18
  Top Layer region: 740 vertices and 1 holes, not listed, extent -133.43,-13.16 17.71,60.09
  Top Layer region: 291 vertices and 0 holes, not listed, extent -198.34,-13.16 -131.58,60.09
  Top Layer region: 294 vertices and 0 holes, not listed, extent -269.74,-13.16 -180.72,82.35
  Top Layer region: -364.31,112.02 -364.31,111.09 -364.31,110.16 -365.24,110.16 -365.24,109.24 -365.24,108.31 -365.24,107.38 -365.24,106.46 -365.24,105.53 -366.17,105.53 -366.17,104.6 -366.17,103.67 -366.17,102.75 -366.17,101.82 -366.17,100.89 -367.1,100.89 -367.1,99.96 -367.1,99.04 -367.1,98.11 -367.1,97.18 -367.1,96.26 -368.02,96.26 -368.02,95.33 -368.02,94.4 -368.02,93.47 -368.02,92.55 -368.02,91.62 -390.28,91.62 -390.28,92.55 -389.35,92.55 -389.35,93.47 -389.35,94.4 -389.35,95.33 -389.35,96.26 -389.35,97.18 -388.42,97.18 -388.42,98.11 -388.42,99.04 -388.42,99.96 -388.42,100.89 -388.42,101.82 -387.5,101.82 -387.5,102.75 -387.5,103.67 -387.5,104.6 -387.5,105.53 -387.5,106.46 -387.5,107.38 -386.57,107.38 -386.57,108.31 -386.57,109.24 -386.57,110.16 -386.57,111.09 -386.57,112.02 -385.64,112.02 -385.64,112.95 -364.31,112.95
  Top Layer region: 247 vertices and 0 holes, not listed, extent -410.68,-12.23 -369.88,82.35
  Top Layer region: 491 vertices and 0 holes, not listed, extent -202.97,-125.36 -128.8,-51.18
  Top Layer region: 1041 vertices and 0 holes, not listed, extent -534,-99.39 -303.12,125
  Top Layer region: 234 vertices and 0 holes, not listed, extent -241.92,-124.43 -208.54,-28.92
  Top Layer lines w7: -542,-134 542,-134 542,134 -542,134 -542,-134
TSW-107-XX-XXX-S [mm] "2.54mm pitch, 7 pin, terminal strip; straight, single row"
  rect 1.65x1.65 hole 1 mask+0: 1(-7.62,-0.025)
  round 1.65 hole 1 mask+0: 2(-5.08,0) 3(-2.54,0) 4(0,0) 5(2.54,0) 6(5.08,0) 7(7.62,0)
  silkscreen extent -9.59,-1.25 8.93,1.25, body extent -8.89,-1.27 8.89,1.27, height 8.38
UX60A-MB-5ST [mm] "USB mini-B Right Angle without positioning post"
  rect 0.5x2 smd: 1(-1.6,8.65) 2(-0.8,8.65) 3(0,8.65) 4(0.8,8.65) 5(1.6,8.65)
  rect 2.5x2.2 smd: 6(-4.2,3.1) 7(-4.2,8.4) 8(4.2,8.4) 9(4.2,3.1)
  Keep-Out Layer region: -3.925,0 3.925,0 3.925,1.725 2.725,1.725 2.725,4.475 3.925,4.475 3.925,7.075 2.725,7.075 2.725,7.425 -2.725,7.425 -2.725,7.075 -3.925,7.075 -3.925,4.475 -2.725,4.475 -2.725,1.725 -3.925,1.725
  silkscreen extent -5.7,0 5.7,10, body extent -5,0 5,10, height 3.95
"WE EFD20-SMD Transformer" [mm] "Tigon Forward Transformer"
  rect 3.9x1.45 smd: 1(-13.05,7.5) 2(-13.05,4.5) 3(-13.05,1.5) 4(-13.05,-1.5) 5(-13.05,-4.5) 6(-13.05,-7.5) 7(13.05,-7.5) 8(13.05,-4.5) 9(13.05,-1.5) 10(13.05,1.5) 11(13.05,4.5) 12(13.05,7.5)
  silkscreen extent -13.17,-11.55 10.7,11.55, body extent -13.26,-11.56 13.26,11.56, height 11.43
"WURTH 7443320680" [mm] "Wurth Inductor 6.8uH - Power Choke WE-HCC"
  rect 3.2x5.4 smd: 1(-5.077,0) 2(5.077,0)
  silkscreen extent -6.78,-5.92 6.76,5.89, body extent -6.78,-5.85 6.68,5.85, height 4

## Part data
BATTERY: ".070 SERIES MULTI-LOCK I/O CONN. 20Pos. PCB 90 Horiz"
C1 C10 C12 C16 C35 C37 C43 C44 C48 C52 C53 C54 C56 C65 C68 C71 C72 C76 C100 C141 C142 C143 C144 C146 C147 C148 C150 C151 C158 C164 C166 C168 C205 C232 C233 C234 C235: "Ceramic, X7R, 25V, 10%"
C2 C228: "Ceramic, X7R, 10V, 10%"
C3 C239 C240: "Ceramic, X5R, 16V, 10%"
C4 C5 C46 C49 C51 C55 C61 C62 C113 C163 C169 C225 C226 C238 C251: "Ceramic, C0G/NP0, 50V, 5%"
C6 C7 C9 C11 C17 C18 C19 C20 C22 C29 C30 C31 C32 C33 C34 C36 C39 C40 C45 C63 C69 C73 C74 C75 C77 C78 C79 C81 C82 C83 C84 C85 C86 C87 C88 C89 C101 C104 C105 C106 C107 C115 C118 C119 C120 C121 C128 C129 C130 C131 C138 C139 C140 C145 C200 C204 C217 C218 C219 C220 C221 C222 C224 C229 C230 C231 C236 C237 C241 C243 C249 C250: "Ceramic, X7R, 16V, 10%"
C8 C67 C70 C155 C156 C170: "Ceramic, X7R, 50V, 10%"
C13 C80: "Ceramic, X7R, 16V, 5%"
C14 C15 C60: "Ceramic, X7R, 16V, 20%"
C21: "TA, 35V, 10%, 0.6Ohm ESR"
C23 C26 C108 C109 C110 C152 C171 C172 C173 C174 C175 C176 C177 C178 C179 C180 C181 C182 C183 C184 C185 C186 C187 C188 C189 C190 C191 C192 C193 C194: "CAP, CERM, 2.2uF, 6.3V, +/-10%, X5R, 0603"
C24 C25 C27 C28: "CAP, CERM, 10pF, 50V, +/-5%, C0G/NP0, 0603"
C38: "CAP, CERM, 0.22uF, 16V, +/-10%, X7R, 0603"
C41 C47: "CAP, CERM, 2.2uF, 25V, +/-10%, X7R, 1210"
C42: "CAP, CERM, 10uF, 25V, +/-10%, X5R, 1210"
C50 C99 C103 C111 C112 C201 C202 C203 C214 C227 C242 C244: "CAP, CERM, 1uF, 16V, +/-10%, X7R, 0603"
C57 C59: "CAP, CERM, 22pF, 50V, +/-5%, C0G/NP0, 0603"
C58: "CAP, CERM, 0.01uF, 100V, +/-10%, X7R, 0805"
C64: "CAP CER 47UF 6.3V X7R 1210"
C66 C102 C122 C123 C124 C125 C132 C133 C134 C135 C157 C215 C216: "Ceramic, X7R, 100V, 10%"
C90 C91: "CAP, CERM, 0.1uF, 16V, +/-10%, X7R, 0603"
C92: "CAP, CERM, 47uF, 6.3V, +/-20%, X5R, 0805"
C93: "CAP, CERM, 33uF, 6.3V, +/-20%, X5R, 1210"
C94 C95: "CAP, CERM, 0.012uF, 16V, +/-10%, X7R, 0603"
C96 C97: "CAP, CERM, 0.027uF, 25V, +/-10%, X7R, 0603"
C98 C126 C127 C136 C137 C149: "Ceramic, X5R, 10V, 10%"
C114: "CAP, CERM, 1000pF, 16V, +/-10%, X7R, 0603"
C117: "CAP, CERM, 330pF, 50V, +/-10%, X7R, 0603"
C159 C165: "CAP, CERM, 10uF, 16V, +/-20%, X7R, 1210"
C160 C161: library part WB_CAPACITOR
C162: "Ceramic, X5R, 16V, 20%"
C167: "Ceramic, C0G/NP0, 50V, 10%"
C196 C197: "Ceramic, X5R, 6.3V, 20%"
C207 C209: "CAP, CERM, 1µF, 100V, +/-20%, C Series, 1206"
C208 C210: "CAP, CERM, 4.7µF, 16V, +/-10%, X5R, 0805"
C248: "CAP TANT 47UF 10V 20% SMD"
C_Vstack1 C_Vstack2 CEXT1 CEXT2 CEXT3 CEXT4: "CAP, CERM, 0.1uF, 100V, +/-10%, X7R, 0805"
CAN_POWER: "CONN 1X3 HEADER 100mil pitch"
D1 D8: "DIODE 2A 30V SMB"
D2 D7: "H-S switching diode"
D3: "DIODE ZENER 3W 30V SMB"
D4 D6 D9: library part TVS_Diode, "Transient Voltage Suppression Diode"
D5: "Diode, Zener, 15V, 225mW, SOT-23"
D10 D45 D51: "Diode, Zener, 15V, 500mW, SOD-123"
D11 D12 D25 D27 D50: "Diode, Ultrafast, 100V, 0.15A, SOD-123"
D13 D14: "Diode, Schottky, 100V, 0.2A, SOD-123"
D15 D24 D44 D49: "Diode, Dual, 200V, 350mW, SOT-23"
D16 D19: "SMT Zener Diode"
D17 D20: "Diode, Schottky, 20V, 1A, SMA"
D18 D22: library part RS1M/B, "1A 1000V Recitfier"
D21 D64: "Diode, Schottky, 30V, 0.2A, SOD-323"
D23 D26 D28: "Diode, Schottky, 80V, 1A, SMA"
D29 D30 D31 D32 D33 D34 D35 D36 D37 D38 D39 D40 D41 D43: "Diode, Zener, 5.6V, 1W, PowerDI123"
D42: "DIODE TVS 64V 400W UNI 5% SMA"
D46: "LED 570NM GREEN DIFF 1206 SMD"
D48: "LED 660NM RED DIFF 1206 SMD"
D53 D54 D55 D56: "TVS ESD BIDIRECT 5V SOD523"
D62 D63: "Diode, Zener, 100V, 550mW, SMB"
Dclamp1 Dclamp2: "Diode, Schottky, 40V, 1A, SOD-123"
F1 F2 F3 F4 F5 F6 F7 F9 F10 F11 F12 F13 F14 F15: "FUSE 8A 125V 6125 FAST SSQ"
F8: "FUSE 12A 125V 6125 FAST SSQ"
F16 F17: "FUSE 2A 63V  FAST ACTING"
F18 F19: "FUSE 2A 125V  FAST ACTING"
J1: "Header, TH, 100mil, 1x7, Gold plated, 230 mil above insulator"
J2 J4: library part "5767096-8 (Mictor 38)", "Mictor Receptacle, SMD 25mil, 19x2, Gold plated, 236 mil above insulator"
J3: "TC2050 plug of nails cable"
J5: "CONN MICRO SD R/A PUSH-PUSH SMD"
J7: "GREY CONN SHROUDED 2x10 HEADER SMT 100mil pitch"
L1 L3 L4 L6 L8 L9: library part "Ferrite Bead", "Ferrite bead, 120mOhm, 2A, 0603"
L5 L7: "Wurth 6.8uH Power Inductor"
L10: "Inductor, Shielded Drum Core, Ferrite, 10uH, 1.7A, 0.065 ohm, SMD"
L11: "Inductor, Shielded Drum Core, Ferrite, 5uH, 2.4A, 0.031 ohm, SMD"
Logo1: library part TI_Logo, "Texas Instrument Corporate Signature"
MNT1 MNT2 MNT3 MNT4 MNT5 MNT6 MNT7 MNT8: library part "4-40 screw mount", "4-40 screw for mounting hardware"
NT3 NT4 NT6: library part NetTie
P1: "CONN RECEPT MINI USB2.0 5POS"
P2: "Tyco .64 Series GET Connector 2 position"
P3: "RJ45 2X1 8 Position Jack"
PING_IN1: "Tyco 025 Series Multi-Lock Connector 4 position"
PING_OFF RT2: "CONN 1X2 HEADER 100mil pitch"
PING_OUT1: "Tyco 025 Series Multi-Lock Connector 8 position"
Q1 Q3 Q5 Q6 Q7 Q8 Q9 Q10 Q14 Q16 Q18 Q19 Q20 Q21 Q22 Q23: library part "SI7938 VER1", "DUAL N CHANNEL MOSFET, 40V, 60A"
Q2 Q4 Q15 Q17: library part SI7938, "DUAL N CHANNEL MOSFET, 40V, 60A"
Q11 Q13 Q24 Q35 Q38 Q41 Q45 Q47: "MOSFET N-CH 60V 115MA SOT323"
Q12 Q44: "MOSFET P-CH 80V 2.2A SOT23-3"
Q25 Q48: library part "BC856B-7-F, Diodes Inc.", "Transistor, PNP, 65V, 0.1A, SOT-23"
Q26 Q32: "MOSFET, P-CH, -150V, -3A, PowerPAK SO-8"
Q27 Q29 Q31 Q34: "45A, 27nC, rDS(on) @ 4.5V =0.0028 ohm"
Q28 Q33: library part "BSC014N03LS G", "100A, 47nC, rDS(on) @ 4.5V =0.0021 Ohm"
Q36: "3A, 17nC, rDS(on) @ 4.5V =0.076 Ohm"
Q37: "MOSFET, P-CH, -20V, -3.7A, SOT-23"
Q40: "MOSFET P-CH 100V 700MA SOT23-3"
Q43: "MOSFET, N-CH, 100V, 0.17A, SOT-323"
Q46: "MOSFET, P-CH, -80V, -23.5A, DDPAK"
Q49: library part "BC846BLT1G, ON Semiconductor", "Transistor, NPN, 65V, 0.1A, SOT-23"
Q52: "MOSFET, P-CH, -80V, -1.2A, SOT-23"
Q53 Q54 Q55 Q57: "PNP, 1.4A, 100V"
Q56: "NPN, 1A, 150V"
R1 R2 R3 R4 R5 R6 R7 R8 R9 R10 R11 R12 R13 R14 R15 R106 R107 R108 R109 R110 R111 R112 R114 R116 R118 R120 R122 R123 R124 R130: "RES, 732 ohm, 1%, 0.1W, 0603"
R16 R134: "RES, 100 ohm, 1%, 0.1W, 0603"
R17: "RES, 60.4k ohm, 1%, 0.1W, 0603"
R18 R22 R24 R26 R36 R39 R47 R52 R64 R65 R77 R78 R79 R82 R89 R113 R115 R117 R119 R121 R128 R131 R146 R147 R149 R151 R159 R167 R168 R169 R173 R177 R180 R183 R185 R191 R195 R198 R199 R215 R221 R226 R227 R228 R236 R239 R246 R247 R248 R249 R251 R255 R256 R257 R283: "1%, 0.1W"
R19 R30: library part CRCW06032K74FKEA, "1%, 0.1W"
R20 R21 R25 R27 R28 R31 R32 R33 R34 R37 R38 R40 R41 R48 R49 R50 R56 R62 R81 R84 R85 R86 R87 R92 R93 R95 R97 R99 R100 R101 R102 R103 R104 R105 R125 R137 R141 R142 R143 R144 R145 R154 R155 R156 R157 R158 R160 R163 R164 R165 R170 R171 R175 R178 R188 R189 R193 R194 R196 R200 R209 R213 R218 R225 R229 R230 R231 R232 R233 R234 R235 R240 R245 R253 R254 R258 R267 R268 R271 R279 R280 R281 R282 R284 R285 R303 R304: "5%, 0.1W"
R23 R29: "RES, 499 ohm, 1%, 0.1W, 0603"
R35: "RES, 787k ohm, 1%, 0.1W, 0603"
R42 R43 R45 R55 R63 R68 R69 R70 R71 R72 R73 R74 R75: "RES, 10.0 ohm, 1%, 0.1W, 0603"
R44 R46 R186: "RES, 47k ohm, 5%, 0.1W, 0603"
R51 R59 R60 R259 R262: "RES, 1.00k ohm, 1%, 0.1W, 0603"
R53 R54 R172 R190: "0.1%, 0.1W"
R57 R243: "RES, 66.5k ohm, 1%, 0.1W, 0603"
R58: "RES, 49.9 ohm, 1%, 0.1W, 0603"
R61: "RES, 9.10k ohm, 1%, 0.1W, 0603"
R66 R67 R94 R98 R216 R223 R241 R242 R244 R250 R252: "0.5%, 0.1W"
R76 R80 R88 R286: "RES, 33 ohm, 5%, 0.1W, 0603"
R83: "RES, 249k ohm, 1%, 0.1W, 0603"
R90 R91: "RES, 1.00k ohm, 1%, 0.063W, 0402"
R96: "RES, 316k ohm, 1%, 0.1W, 0603"
R126: "RES, 133k ohm, 1%, 0.1W, 0603"
R127 R237 R238: "RES, 402k ohm, 1%, 0.1W, 0603"
R129: "1%, 0.125W"
R132: "RES, 8.2k ohm, 5%, 0.1W, 0603"
R133: "RES, 10.2k ohm, 1%, 0.1W, 0603"
R135: "RES, 51k ohm, 5%, 0.1W, 0603"
R136: "RES, 10.7k ohm, 1%, 0.1W, 0603"
R138: "RES, 54.9k ohm, 1%, 0.1W, 0603"
R139: "RES, 17.8k ohm, 1%, 0.1W, 0603"
R140 R219: "RES, 10.0k ohm, 1%, 0.1W, 0603"
R148 R176: "RES, 442k ohm, 1%, 0.1W, 0603"
R150: "RES, 174k ohm, 1%, 0.1W, 0603"
R152: "RES, 26.7k ohm, 1%, 0.1W, 0603"
R153 R187: "RES, 5.90k ohm, 1%, 0.1W, 0603"
R161 R162 R181 R182: "RES, 560 ohm, 5%, 0.1W, 0603"
R166: "22 Ohm 1%, 1W"
R174 R192: "RES, 0.01 ohm, 1%, 1W, 2010 SMD"
R179 R197: "RES, 0.033 ohm, 1%, 0.5W, 1812 SMD"
R184: "RES, 1.10k ohm, 1%, 0.1W, 0603"
R201 R202 R203 R204 R205 R206 R207 R208 R260 R263 R265 R269 R278: "RES, 20.0k ohm, 1%, 0.1W, 0603"
R210: "RES, 910k ohm, 5%, 0.1W, 0603"
R211: "RES, 150k ohm, 5%, 0.1W, 0603"
R212 R217: "1%, 0.25W"
R214 R220: "5%, 0.125W"
R222: "RES, 75.0k ohm, 1%, 0.1W, 0603"
R224: "RES, 0.27 ohm, 1%, 0.5W, 1210 SMD"
R261 R264 R273: "RES, 100k ohm, 1%, 0.1W, 0603"
R266 R270: "RES, 680k ohm, 1%, 0.1W, 0603"
R272: "RES, 39.0k ohm, 1%, 0.1W, 0603"
R274: "RES, 82.0k ohm, 1%, 0.1W, 0603"
R275 R277: "RES, 25.5k ohm, 1%, 0.1W, 0603"
R276: "RES, 1.50k ohm, 1%, 0.1W, 0603"
RT1: "Thermistor NTC, 100k ohm, 1%, 0603"
SERIAL_PORT: "CONN 1X6 HEADER 100mil pitch"
SW1: "Switch, Normally open, 2.3N force, 200k operations, SMD"
T1: "Wurth 749196111 flyback transformer"
T2 T3: library part EFD20-SMD, "Forward Transformer"
T5: "CHOKE COMM MODE 1000 OHM .5A SMD"
TEMP_SENSE: "Tyco 025 Series Multi-Lock Connector 16 position"
TEST_PORT: "20Pin AMP Connector VERT HEADER"
TP1 TP2 TP3 TP5: "TEST POINT.  No entry in BOM."
U1 U46: "SOT-23 Precision Low Dropout Voltage Reference"
U2: "14 channel AFE"
U3: "14-Bit, 50 kSPS to 250 kSPS, Differential Input, Micro Power A/D Converter"
U4: library part ISO7251, "Low Power 3-Channel Digital Isolator"
U5: library part SN65HVDA1040A, "CAN transceiver"
U6 U26: "12 channel Gate Controller"
U7: library part AGL030V2-QN48, "IGLOO Low-Power Flash 1.2/1.5V FPGA with Flash*Freeze, 34 User IOs, 30K System Gates, 1Kbit Flash ROM, 48-Pin QFN, Commercial Grade"
U8: "5-Pin Microprocessor Reset Circuits"
U9: "Dual 150mA Ultra Low-Dropout Regulator"
U10: library part TPS7A4001, "VREG, LDO, ADJ, 50mA, MSOP8"
U11: "Dual 2A, 500kHz Wide Input Range Buck Regulator, 16-pin TSSOP-EP, Pb-Free"
U12 U30: "Dual 5A Compound Gate Driver"
U13: "Low Noise Regulated Switched Capacitor Voltage Inverter"
U14: "Stellaris ARM Cortex-M3 Microcontroller"
U15: "TVS ESD BIDIRECT 5V SOT-666"
U16: "Adjustable Precision Zener Shunt Regulator"
U17 U38: "DIODE ARRAY ESD 6.1V Breakdown"
U18: "Battery Stack Protection WCOMP"
U19: "Oscillator, 8.000MHz, 3.3V, SMD"
U20: library part ISO7250, "Low Power 3-Channel Digital Isolator"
